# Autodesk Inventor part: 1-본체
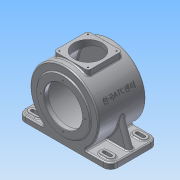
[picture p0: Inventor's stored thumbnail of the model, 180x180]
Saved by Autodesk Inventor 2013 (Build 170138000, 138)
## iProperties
Created: 2015-06
Part Number: 1-본체
Material: 알루미늄 6061
Document SubType Name: Modeling
Designer: ST3
Density: 2.71 g/cm^3
Mass: 3276.32 g
Surface Area: 2302.91 cm^2
Volume: 1208.98 cm^3
Author: ST3
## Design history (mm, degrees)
sketch "스케치1"
  geometry: C1 r 85 at (0, 0); 1 further point
  constraints: 1 centre point, 1 coincident
  dimensions: "d0" = 170 diameter of C1
extrude "돌출1" new body sketch "스케치1" distance "d2" = 118; taper "d3" = 0 deg
node "작업 평면1"
node "작업 평면3"
sketch "스케치4"
  geometry: L1 (42.5, 16.5)-(-42.5, 16.5); L2 (-42.5, 16.5)-(-42.5, 101.5); L3 (-42.5, 101.5)-(42.5, 101.5); L4 (42.5, 101.5)-(42.5, 16.5); L5 (85, 118)-(-85, 118) reference; L6 (-85, 0)-(85, 0) reference; L7 (-85, 0)-(-85, 118) reference; L8 (85, 0)-(85, 118) reference; 5 further points
  constraints: 8 end point, 4 midpoint, 2 parallel, 1 horizontal, 1 horizontal alignment, 1 perpendicular, 1 vertical alignment
  dimensions: "d13" = 85 distance of L1.start L1.end; "d15" = 85 distance of L3.end L1.start
extrude "돌출3" join sketch "스케치4" stored distance "d16" = 88; taper "d17" = 0 deg
sketch "스케치5"
  geometry: L1 (-42.5, -16.5)-(42.5, -16.5) reference; L2 (-42.5, -101.5)-(-42.5, -16.5) reference; C1 r 35 at (0, -59); 3 further points
  constraints: 2 midpoint, 1 centre point, 1 horizontal alignment, 1 vertical alignment
  dimensions: "d18" = 70 diameter of C1
sketch "스케치6"
  geometry: A1 r 50.205 centre (0, -59) between (-35.5, -23.5) and (35.5, -23.5); 3 further points
  constraints: 4 point on circle, 2 horizontal alignment, 2 vertical alignment, 1 centre point
  dimensions: "d22" = 71 distance of A1.end A1.start; "d24" = 71 distance of point (-35.5, -94.5) A1.start
hole "구멍1" sketch "스케치6" at (-35.5, -23.5), (35.5, -23.5), (-35.5, -94.5), (35.5, -94.5) diameter "d25" = 3.242; stored, may be unused: countersink angle "d29" = 90 deg, drill point angle "d31" = 118 deg; dims "d26" = 10, "d27" = 4, "d28" = 2, "d30" = 13
node "작업 평면7"
sketch "스케치7"
  geometry: L1 (-42.5, 101.5)-(-42.5, 16.5) reference; L2 (-42.5, 16.5)-(42.5, 16.5) reference; L3 (42.5, 16.5)-(42.5, 101.5) reference; L4 (42.5, 101.5)-(-42.5, 101.5) reference; L5 (85, 118)-(-85, 118) reference; L6 (-85, 0)-(85, 0) reference; L7 (-85, 118)-(-115, 118); L8 (-115, 118)-(-115, 0); L9 (-115, 0)-(-85, 0); L10 (85, 0)-(115, 0); L11 (115, 0)-(115, 118); L12 (115, 118)-(85, 118); 2 further points
  constraints: 12 end point, 2 horizontal, 2 parallel, 1 midpoint, 1 perpendicular, 1 vertical
  dimensions: "d35" = 230 distance between parallel lines of L11 L8; "d37" = 115 distance from line of L11 point (0, 118)
extrude "돌출5" join sketch "스케치7" distance "d38" = 14; taper "d39" = 0 deg
sketch "스케치2"
  geometry: C1 r 77 at (0, 0); 1 further point
  constraints: 1 centre point, 1 coincident
  dimensions: "d4" = 154 diameter of C1
extrude "돌출2" cut sketch "스케치2" stored distance "d6" = 102; taper "d7" = 0 deg
extrude "돌출6" cut sketch "스케치5" stored distance "d40" = 14; taper "d41" = 0 deg
sketch "스케치8"
  geometry: C1 r 65 at (0, 0); A1 r 85 centre (0, 0) between (46.733, -71) and (-46.733, -71) reference
  constraints: 1 centre point, 1 coincident
  dimensions: "d42" = 130 diameter of C1
extrude "돌출7" join sketch "스케치8" distance "d44" = 3; taper "d45" = 0 deg
sketch "스케치9"
  geometry: C1 r 65 at (0, 0); A1 r 85 centre (0, 0) between (46.733, -71) and (-46.733, -71) reference
  constraints: 1 centre point, 1 coincident
  dimensions: "d46" = 130 diameter of C1
extrude "돌출8" join sketch "스케치9" distance "d48" = 13; taper "d49" = 0 deg
sketch "스케치13"
  geometry: C1 r 65 at (0, 0) reference; C2 r 47.5 at (0, 0)
  constraints: 1 centre point, 1 coincident
  dimensions: "d63" = 95 diameter of C2
extrude "돌출9" cut sketch "스케치13" stored distance "d65" = 13; taper "d66" = 0 deg
sketch "스케치14"
  geometry: C1 r 77 at (0, 0) reference; C2 r 31 at (0, 0)
  constraints: 1 centre point, 1 coincident
  dimensions: "d67" = 62 diameter of C2
extrude "돌출10" join sketch "스케치14" distance "d69" = 3.5; taper "d70" = -25 deg
sketch "스케치16"
  geometry: C1 r 29.368 at (0, 0) reference; C2 r 23.5 at (0, 0); C3 r 15 at (0, 0)
  constraints: 2 centre point, 2 coincident
  dimensions: "d71" = 47 diameter of C2; "d73" = 30 diameter of C3
extrude "돌출11" cut sketch "스케치16" distance "d74" = 14; taper "d75" = 0 deg
extrude "돌출12" cut sketch "스케치16" distance "d76" = 17; taper "d77" = 0 deg
sketch "스케치17"
  geometry: C1 r 47.5 at (0, 0) reference; C2 r 65 at (0, 0) reference; A1 r 55 centre (0, 0) between (0, 55) and (-55, 0); 2 further points
  constraints: 4 point on circle, 2 horizontal alignment, 2 vertical alignment, 1 centre point, 1 coincident
  dimensions: "d78" = 110 diameter of A1
hole "구멍2" sketch "스케치17" at (0, 55), (-55, 0), (55, 0), (0, -55) diameter "d80" = 3.242; stored, may be unused: countersink angle "d84" = 90 deg, drill point angle "d86" = 118 deg; dims "d81" = 10, "d82" = 4, "d83" = 2, "d85" = 13
node "작업 평면12"
sketch "스케치19"
  geometry: L1 (0, 0)-(77.036, 35.923); L2 (0, 0)-(23.5, 0); C1 r 15 at (0, 0) reference; A1 r 85 centre (0, 0) between (46.733, -71) and (-46.733, -71) reference
  constraints: 4 end point, 1 horizontal, 1 horizontal alignment, 1 point on circle, 1 other
  dimensions: "d87" = 25 deg angle of L2 L1
  node "투영된 루프7"
node "작업 평면13"
sketch "스케치20"
  geometry: 5 further points
  constraints: 1 coincident, 1 other
feature "엠보싱1" sketch "스케치20" dims "d88" = 0.5, "d89" = 0
sketch "스케치21"
  geometry: L1 (-115, 0)-(-115, -118) reference; L2 (-115, -118)-(-46.733, -118) reference; L3 (-97, -9)-(-81, -9); L4 (-97, -27)-(-81, -27); L5 (81, -9)-(97, -9); L6 (81, -27)-(97, -27); L7 (81, -91)-(97, -91); L8 (81, -91)-(97, -91); L9 (-97, -91)-(-81, -91); L10 (-97, -109)-(-81, -109); L11 (81, -109)-(97, -109); A1 r 9 centre (-97, -18) between (-97, -9) and (-97, -27); A2 r 9 centre (-81, -18) between (-81, -9) and (-81, -27); A3 r 9 centre (-97, -100) between (-97, -91) and (-97, -109); A4 r 9 centre (-81, -100) between (-81, -91) and (-81, -109); A5 r 9 centre (81, -18) between (81, -9) and (81, -27); A6 r 9 centre (97, -18) between (97, -9) and (97, -27); A7 r 9 centre (81, -100) between (81, -91) and (81, -91); A8 r 9 centre (97, -100) between (97, -91) and (97, -91); 2 further points
  constraints: 18 end point, 18 point on circle, 13 tangent, 8 centre point, 7 equal radius, 6 horizontal alignment, 4 vertical alignment, 3 parallel, 2 collinear, 1 midpoint
  dimensions: "d90" = 16 distance of A2.centre A1.centre; "d92" = 16 distance of A6.centre A5.centre; "d93" = 82 distance of A3.centre A1.centre; "d94" = 41 vertical distance of point (-115, -59) A1.centre; "d95" = 194 distance of A6.centre A1.centre; "d96" = 18 diameter of A1; "d97" = 97 horizontal distance of point (0, 0) A1.centre
extrude "돌출13" join sketch "스케치21" distance "d98" = 3; taper "d99" = 0 deg
sketch "스케치22"
  geometry: L1 (-81, -91)-(-97, -91) reference; L2 (-97, -109)-(-81, -109) reference; L3 (115, -118)-(-115, -118) reference; L4 (-115, -118)-(-115, 0) reference; L5 (-115, 0)-(115, 0) reference; L6 (115, 0)-(115, -118) reference; L7 (-97, -9)-(-81, -9) reference; L8 (-81, -27)-(-97, -27) reference; L9 (81, -91)-(97, -91) reference; L10 (97, -109)-(81, -109) reference; L11 (81, -9)-(97, -9) reference; L12 (97, -27)-(81, -27) reference; L13 (97, -14)-(81, -14); L14 (81, -22)-(97, -22); L15 (97, -96)-(81, -96); L16 (81, -104)-(97, -104); L17 (-97, -96)-(-81, -96); L18 (-81, -104)-(-97, -104); L19 (-81, -14)-(-97, -14); L20 (-97, -22)-(-81, -22); A1 r 9 centre (-97, -100) between (-97, -91) and (-97, -109) reference; A2 r 9 centre (-81, -100) between (-81, -109) and (-81, -91) reference; A3 r 9 centre (-97, -18) between (-97, -9) and (-97, -27) reference; A4 r 9 centre (-81, -18) between (-81, -27) and (-81, -9) reference; A5 r 9 centre (81, -100) between (81, -91) and (81, -109) reference; A6 r 9 centre (97, -100) between (97, -109) and (97, -91) reference; A7 r 9 centre (81, -18) between (81, -9) and (81, -27) reference; A8 r 9 centre (97, -18) between (97, -27) and (97, -9) reference; A9 r 4 centre (81, -18) between (81, -14) and (81, -22); A10 r 4 centre (97, -18) between (97, -22) and (97, -14); A11 r 4 centre (81, -100) between (81, -96) and (81, -104); A12 r 4 centre (97, -100) between (97, -104) and (97, -96); A13 r 4 centre (-81, -100) between (-81, -104) and (-81, -96); A14 r 4 centre (-97, -100) between (-97, -96) and (-97, -104); A15 r 4 centre (-97, -18) between (-97, -14) and (-97, -22); A16 r 4 centre (-81, -18) between (-81, -22) and (-81, -14); 1 further point
  constraints: 16 end point, 16 point on circle, 8 centre point, 12 other
  dimensions: "d101" = 8 distance between parallel lines of L20 L19; "d103" = 8 distance between parallel lines of L18 L17; "d104" = 8 distance between parallel lines of L16 L15; "d105" = 8 distance between parallel lines of L14 L13
extrude "돌출14" cut sketch "스케치22" stored distance "d106" = 3; taper "d107" = 0 deg
node "작업 평면15"
sketch "스케치23"
  geometry: L1 (115, -71)-(46.733, -71) reference; L2 (115, -85)-(115, -71) reference; L3 (-115, -85)-(115, -85) reference; L4 (-115, -85)-(-115, -71) reference; L5 (-46.733, -71)-(-115, -71) reference; L6 (-109, -71)-(-84.87, -4.703); L7 (84.87, -4.703)-(109, -71); C1 r 65 at (0, 0) reference; A1 r 85 centre (0, 0) between (46.733, -71) and (-46.733, -71) reference; 1 further point
  constraints: 4 end point, 2 point on circle, 2 point on line
  dimensions: "d109" = 6 distance of L4.end L6.start; "d110" = 6 distance of L1.start L7.end; "d111" = 110 deg angle of L5 L6; "d112" = 110 deg angle of L1 L7
  node "투영된 루프9"
feature "리브1" dims "d113" = 1, "d114" = 15, "d115" = 0, "d116" = 0, "d117" = 1, "d118" = 1
feature "리브2" dims "d119" = 1, "d120" = 15, "d121" = 0, "d122" = 0, "d123" = 1, "d124" = 1
fillet "모깎기1" dims "d125" = 18
fillet "모깎기2" dims "d126" = 0.3
fillet "모깎기3" dims "d127" = 3
chamfer "모따기1" distance "d128" = 1; stored, may be unused: second distance "d129" = 2, angle "d130" = 45 deg
fillet "모깎기4" dims "d131" = 7.5
fillet "모깎기5" dims "d132" = 3
fillet "모깎기6" dims "d133" = 7
fillet "모깎기7" dims "d134" = 3
fillet "모깎기8" dims "d135" = 3
fillet "모깎기9" dims "d136" = 3
fillet "모깎기10" dims "d137" = 3
fillet "모깎기11" dims "d138" = 3
fillet "모깎기12" dims "d139" = 3
node "솔리드1"
node "투영된 루프2"
node "투영된 루프3"
node "투영된 루프8"
other parameters: "d12" = 88, "d34" = -85, "d108" = -59
